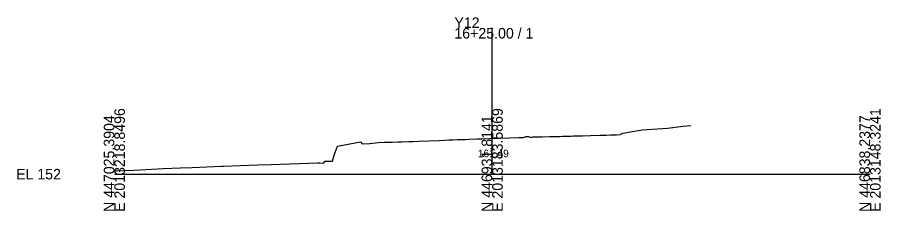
# Model space of a CAD drawing. Extents: x -26 to 1203, y -10 to 9542.
# Drawn here: x 974.3 to 1202.8, y 2490.3 to 2541.6 of the extents above; entities that cross this region are included whole.
import ezdxf

# ---------------------------------------------------------------- set-up
doc = ezdxf.new("R2010")
doc.units = 0
for name, color, linetype in [('Default', 7, 'Continuous'), ('Exist Cross Section Cell', 7, 'Continuous'), ('Exist XS Center Line Elevation Label', 7, 'Continuous'), ('Exist XS Ground Line', 7, 'Continuous')]:
    doc.layers.add(name, color=color, linetype=linetype)

msp = doc.modelspace()

# ---------------------------------------------------------------- linework, layer by layer
at = {"layer": 'Exist Cross Section Cell'}
for p, q in [((1100, 2500), (1100, 2538.74)), ((1000, 2500), (1100, 2500)), ((1100, 2500), (1200, 2500))]:
    msp.add_line(p, q, dxfattribs=at)
at = {"layer": 'Exist XS Ground Line'}
msp.add_lwpolyline([(1000, 2500.86), (1000.55, 2500.88), (1005.12, 2501.04), (1006.84, 2501.14), (1012.88, 2501.46), (1017.52, 2501.64), (1020.64, 2501.81), (1028.4, 2502.09), (1028.91, 2502.11), (1037.89, 2502.49), (1041.4, 2502.6), (1053.83, 2503.01), (1054.42, 2502.97), (1055.33, 2502.91), (1055.83, 2503.41), (1056.91, 2503.46), (1057.7, 2503.48), (1058.29, 2505.29), (1059.03, 2507.46), (1065.12, 2508.56), (1065.62, 2508.06), (1067.62, 2508.16), (1069.82, 2508.39), (1071.54, 2508.45), (1072.49, 2508.48), (1073.49, 2508.52), (1075.15, 2508.57), (1076.11, 2508.61), (1077.94, 2508.67), (1078.43, 2508.67), (1078.97, 2508.69), (1080.52, 2508.76), (1083.21, 2508.86), (1085.84, 2508.96), (1087.47, 2509.03), (1088.5, 2509.07), (1089.17, 2509.1), (1089.55, 2509.11), (1090.86, 2509.15), (1091.17, 2509.16), (1092.86, 2509.2), (1093.84, 2509.24), (1096.01, 2509.32), (1096.73, 2509.35), (1097.29, 2509.37), (1099.39, 2509.47), (1100.25, 2509.5), (1100.71, 2509.52), (1101.86, 2509.56), (1104.56, 2509.65), (1107.08, 2509.73), (1107.54, 2509.74), (1108.28, 2509.71), (1108.88, 2510.01), (1109.65, 2510), (1110.25, 2509.7), (1110.77, 2509.89), (1111.74, 2509.91), (1112.58, 2509.92), (1113.19, 2509.93), (1115.25, 2509.97), (1117.49, 2510.02), (1117.92, 2510.02), (1118.63, 2510.04), (1120.85, 2510.1), (1121.55, 2510.13), (1123.23, 2510.18), (1123.9, 2510.19), (1126.05, 2510.25), (1128.57, 2510.31), (1130.18, 2510.36), (1131.36, 2510.4), (1131.79, 2510.41), (1132.1, 2510.41), (1132.9, 2510.44), (1133.92, 2510.47), (1134.6, 2510.88), (1139.74, 2511.74), (1146.37, 2512.2), (1150.58, 2512.68), (1152.62, 2512.91)], dxfattribs=at)

# ---------------------------------------------------------------- texts
at = {"layer": 'Default'}
msp.add_text('-', height=0.0001, dxfattribs=at).set_placement((1000, 2500))
at = {"layer": 'Exist Cross Section Cell'}
for s, p in [('Y12', (1090, 2538.74)), ('16+25.00 / 1', (1090, 2535.94)), ('EL 152', (974, 2498.6))]:
    msp.add_text(s, height=2.8, dxfattribs=at).set_placement(p)
for s, p in [('E 2013218.8496', (1002.8, 2490)), ('E 2013183.5869', (1102.8, 2490)), ('E 2013148.3241', (1202.8, 2490)), ('N 447025.3904', (1000, 2490)), ('N 446931.8141', (1100, 2490)), ('N 446838.2377', (1200, 2490))]:
    msp.add_text(s, height=2.8, rotation=90, dxfattribs=at).set_placement(p)
at = {"layer": 'Exist XS Center Line Elevation Label'}
msp.add_text('161.49', height=2, dxfattribs=at).set_placement((1096.21, 2504.49))

doc.saveas('drawing.dxf')
